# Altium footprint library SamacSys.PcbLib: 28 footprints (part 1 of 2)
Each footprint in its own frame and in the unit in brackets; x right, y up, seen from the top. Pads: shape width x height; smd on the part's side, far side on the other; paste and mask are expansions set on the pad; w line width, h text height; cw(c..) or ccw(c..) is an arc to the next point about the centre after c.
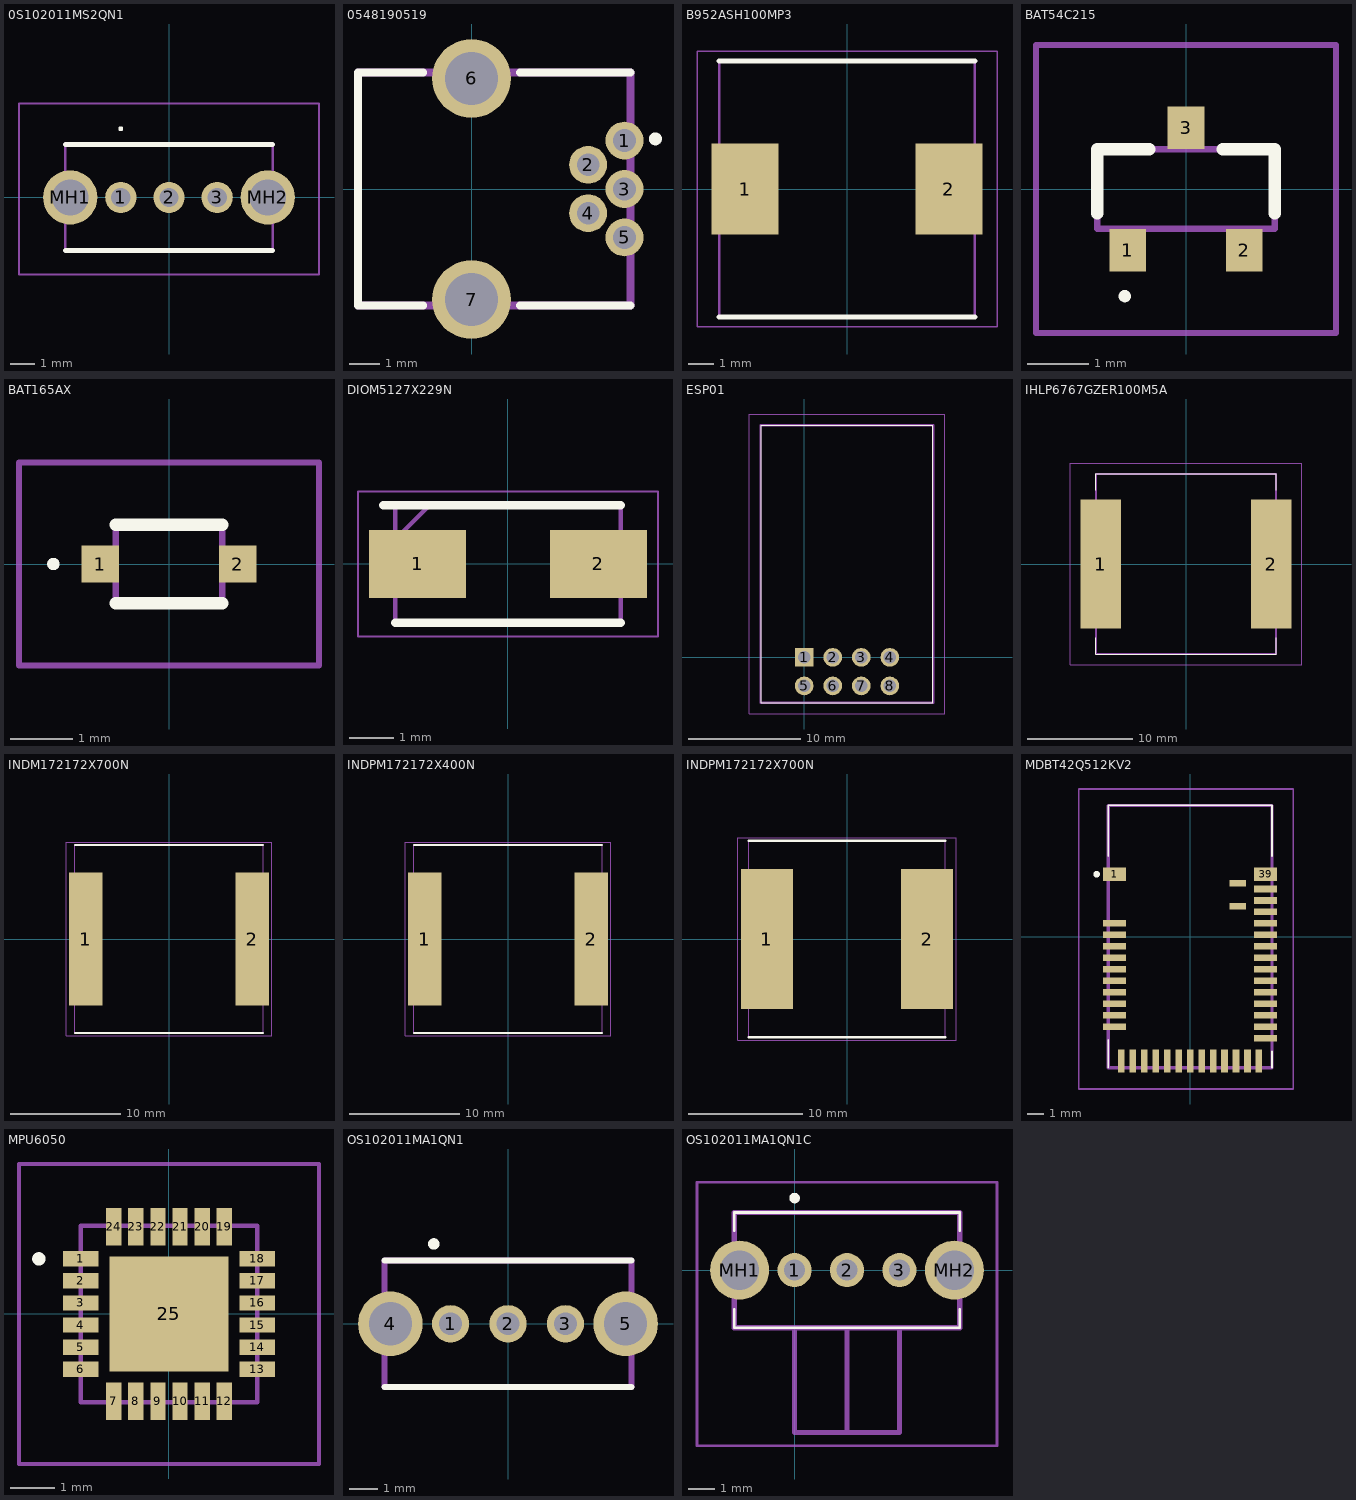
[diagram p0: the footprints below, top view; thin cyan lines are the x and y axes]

## 0S102011MS2QN1 [mm]
pads (5):
  round 1.3 hole 0.8: 1(-2,0) 2(0,0) 3(2,0)
  round 2.25 hole 1.5: MH1(-4.1,0) MH2(4.1,0)
Top Overlay:
  lines w0.1: -2,2.8 cw(c-2,2.85) -2,2.9 cw(c-2,2.85) -2,2.8
  lines w0.2: -4.3,-2.2 4.3,-2.2 ; -4.3,2.2 4.3,2.2
Mechanical 13:
  lines w0.1: -4.3,-2.15 -4.3,2.15 4.3,2.15 4.3,-2.15 -4.3,-2.15
Mechanical 15:
  lines w0.1: -6.225,-3.2 -6.225,3.9 6.225,3.9 6.225,-3.2 -6.225,-3.2
3D body "0S102011MS2QN1.stp": height 8.8, standoff -5, extent -4.745,-2.15 4.75,2.15

## 0548190519 [mm]
pads (7):
  round 1.25 hole 0.75: 1(5.05,1.6) 2(3.85,0.8) 3(5.05,0) 4(3.85,-0.8) 5(5.05,-1.6)
  round 2.6 hole 1.75: 6(0,3.65) 7(0,-3.65)
Top Overlay:
  circle w0.254: c6.071,1.655 r0.085
  lines w0.254: -1.6,-3.85 -3.75,-3.85 -3.75,3.85 -1.6,3.85 ; 1.6,-3.85 5.25,-3.85 ; 1.6,3.85 5.25,3.85
Mechanical 13:
  lines w0.254: -3.75,-3.85 5.25,-3.85 5.25,3.85 -3.75,3.85 -3.75,-3.85

## B952ASH100MP3 [mm]
pads (2):
  rect 2.65x3.6 smd: 1(-4.025,0) 2(4.025,0)
Top Overlay:
  lines w0.2: -5.05,-5.05 5.05,-5.05 ; -5.05,5.05 5.05,5.05
Mechanical 13:
  lines w0.1: -5.05,-5.05 5.05,-5.05 5.05,5.05 -5.05,5.05 -5.05,-5.05
Mechanical 15:
  lines w0.05: -5.925,-5.45 5.925,-5.45 5.925,5.45 -5.925,5.45 -5.925,-5.45
3D body "#B952AS-H-100M=P3.stp": height 4.9, standoff 0, extent -5.085,-5.05 5.085,5.05

## BAT54C215 [mm]
pads (3):
  rect 0.6x0.7 smd: 1(-0.95,-1) 2(0.95,-1) 3(0,1)
Top Overlay:
  lines w0.1: -1,-1.8 cw(c-1,-1.75) -1,-1.7 cw(c-1,-1.75) -1,-1.8
  lines w0.2: -1.45,-0.4 -1.45,0.65 -0.6,0.65 ; 0.6,0.65 1.45,0.65 1.45,-0.4
Mechanical 13:
  lines w0.1: -1.45,-0.65 -1.45,0.65 1.45,0.65 1.45,-0.65 -1.45,-0.65
Mechanical 15:
  lines w0.1: -2.45,-2.35 -2.45,2.35 2.45,2.35 2.45,-2.35 -2.45,-2.35
3D body "BAT54C,215.stp": height 0.95, standoff 0, extent -1.452,-1.201 1.448,1.199

## BAT165AX [mm]
pads (2):
  rect 0.6x0.6 smd: 1(-1.1,0) 2(1.1,0)
Top Overlay:
  lines w0.1: -1.9,0 cw(c-1.85,0) -1.8,0 cw(c-1.85,0) -1.9,0
  lines w0.2: -0.85,-0.625 0.85,-0.625 ; -0.85,0.625 0.85,0.625
Mechanical 13:
  lines w0.1: -0.85,-0.625 -0.85,0.625 0.85,0.625 0.85,-0.625 -0.85,-0.625
Mechanical 15:
  lines w0.1: -2.4,-1.625 -2.4,1.625 2.4,1.625 2.4,-1.625 -2.4,-1.625
3D body "BAT165AX.stp": height 0.93, standoff 0, extent -1.244,-0.623 1.245,0.627

## DIOM5127X229N [mm]
pads (2):
  rect 2.2x1.55 smd: 1(-2.05,0) 2(2.05,0)
Top Overlay:
  lines w0.2: -2.825,1.332 2.552,1.332 ; -2.552,-1.332 2.552,-1.332
Mechanical 13:
  lines w0.1: -2.552,0.558 -1.778,1.332 ; -2.552,-1.332 -2.552,1.332 2.552,1.332 2.552,-1.332 -2.552,-1.332
Mechanical 15:
  lines w0.05: -3.4,-1.645 -3.4,1.645 3.4,1.645 3.4,-1.645 -3.4,-1.645
3D body "ES1D-E3_61T.stp": height 2.29, standoff 0, extent -2.552,-1.332 2.552,1.332

## ESP01 [mm]
pads (8):
  rect 1.665x1.665 hole 1.11: 1(0,0)
  round 1.665 hole 1.11: 2(2.54,0) 3(5.08,0) 4(7.62,0) 5(0,-2.54) 6(2.54,-2.54) 7(5.08,-2.54) 8(7.62,-2.54)
Top Overlay:
  lines w0.1: -3.81,-4.04 -3.81,20.66 11.43,20.66 11.43,-4.04 -3.81,-4.04
Mechanical 13:
  lines w0.2: -3.89,-4.04 -3.89,20.66 11.51,20.66 11.51,-4.04 -3.89,-4.04
Mechanical 15:
  lines w0.1: -4.89,-5.04 -4.89,21.66 12.51,21.66 12.51,-5.04 -4.89,-5.04
3D body "ESP-01.stp": height 2.75, standoff 0, extent -3.56,-3.98 10.84,20.72

## IHLP6767GZER100M5A [mm]
pads (2):
  rect 3.825x12.32 smd: 1(-8.123,0) 2(8.123,0)
Top Overlay:
  lines w0.1: -8.575,-7 -8.575,-8.575 8.575,-8.575 8.575,-7 ; -8.575,7 -8.575,8.575 8.575,8.575 8.575,7
Mechanical 13:
  lines w0.2: -8.575,-8.575 -8.575,8.575 8.575,8.575 8.575,-8.575 -8.575,-8.575
Mechanical 15:
  lines w0.1: -11.035,-9.575 -11.035,9.575 11.035,9.575 11.035,-9.575 -11.035,-9.575
3D body "IHLP6767GZER100M5A.stp": height 6.89, standoff 0, extent -8.584,-8.592 8.591,8.584

## INDM172172X700N [mm]
pads (2):
  rect 3.05x12.15 smd: 1(-7.6,0) 2(7.6,0)
Top Overlay:
  lines w0.2: -8.575,-8.575 8.575,-8.575 ; -8.575,8.575 8.575,8.575
Mechanical 13:
  lines w0.1: -8.575,-8.575 -8.575,8.575 8.575,8.575 8.575,-8.575 -8.575,-8.575
Mechanical 15:
  lines w0.05: -9.375,-8.825 -9.375,8.825 9.375,8.825 9.375,-8.825 -9.375,-8.825
3D body "IHLP6767GZER101M11.stp": height 6.89, standoff 0, extent -8.584,-8.592 8.591,8.584

## INDPM172172X400N [mm]
pads (2):
  rect 3.05x12.15 smd: 1(-7.6,0) 2(7.6,0)
Top Overlay:
  lines w0.2: -8.575,-8.575 8.575,-8.575 ; -8.575,8.575 8.575,8.575
Mechanical 13:
  lines w0.1: -8.575,-8.575 -8.575,8.575 8.575,8.575 8.575,-8.575 -8.575,-8.575
Mechanical 15:
  lines w0.05: -9.375,-8.825 -9.375,8.825 9.375,8.825 9.375,-8.825 -9.375,-8.825
3D body "IHLP6767DZER4R7M01.stp": height 3.91, standoff 0, extent -8.584,-8.592 8.591,8.584

## INDPM172172X700N [mm]
pads (2):
  rect 4.55x12.2 smd: 1(-7,0) 2(7,0)
Top Overlay:
  lines w0.2: -8.575,-8.575 8.575,-8.575 ; -8.575,8.575 8.575,8.575
Mechanical 13:
  lines w0.1: -8.575,-8.575 -8.575,8.575 8.575,8.575 8.575,-8.575 -8.575,-8.575
Mechanical 15:
  lines w0.05: -9.525,-8.825 -9.525,8.825 9.525,8.825 9.525,-8.825 -9.525,-8.825
3D body "1234772.stp": height 7, standoff 0, extent -8.575,-8.575 8.575,8.575

## MDBT42Q512KV2 [mm]
pads (41):
  rect 1.4x0.8 smd: 1(-4.6,3.8) 39(4.6,3.8)
  rect 1.4x0.4 smd: 2(-4.6,0.8) 3(-4.6,0.1) 4(-4.6,-0.6) 5(-4.6,-1.3) 6(-4.6,-2) 7(-4.6,-2.7) 8(-4.6,-3.4) 9(-4.6,-4.1) 10(-4.6,-4.8) 11(-4.6,-5.5) 25(4.6,-6.2) 26(4.6,-5.5) 27(4.6,-4.8) 28(4.6,-4.1) 29(4.6,-3.4) 30(4.6,-2.7) 31(4.6,-2) 32(4.6,-1.3) 33(4.6,-0.6) 34(4.6,0.1) 35(4.6,0.8) 36(4.6,1.5) 37(4.6,2.2) 38(4.6,2.9)
  rect 0.4x1.4 smd: 12(-4.2,-7.6) 13(-3.5,-7.6) 14(-2.8,-7.6) 15(-2.1,-7.6) 16(-1.4,-7.6) 17(-0.7,-7.6) 18(0,-7.6) 19(0.7,-7.6) 20(1.4,-7.6) 21(2.1,-7.6) 22(2.8,-7.6) 23(3.5,-7.6) 24(4.2,-7.6)
  rect 1x0.4 smd: 40(2.9,3.25) 41(2.9,1.85)
Top Overlay:
  lines w0.1: -5,-8 -5,-6.3 ; -5,4.9 -5,8 4.9,8 5,8 5,4.9 ; 5,-8 5,-7
  lines w0.2: -5.7,3.7 cw(c-5.7,3.8) -5.7,3.9 cw(c-5.7,3.8) -5.7,3.7
Mechanical 13:
  lines w0.2: -5,-8 -5,8 5,8 5,-8 -5,-8
Mechanical 15:
  lines w0.1: -6.8,-9.3 -6.8,9 6.3,9 6.3,-9.3 -6.8,-9.3
3D body "MDBT42Q-512KV2.stp": height 2.3, standoff 0, extent -5,-8 5,8

## MPU6050 [mm]
pads (25):
  rect 0.8x0.35 smd: 1(-2,1.25) 2(-2,0.75) 3(-2,0.25) 4(-2,-0.25) 5(-2,-0.75) 6(-2,-1.25) 13(2,-1.25) 14(2,-0.75) 15(2,-0.25) 16(2,0.25) 17(2,0.75) 18(2,1.25)
  rect 0.35x0.85 smd: 7(-1.25,-1.975) 8(-0.75,-1.975) 9(-0.25,-1.975) 10(0.25,-1.975) 11(0.75,-1.975) 12(1.25,-1.975) 19(1.25,1.975) 20(0.75,1.975) 21(0.25,1.975) 22(-0.25,1.975) 23(-0.75,1.975) 24(-1.25,1.975)
  rect 2.7x2.6 smd: 25(0,0)
Top Overlay:
  lines w0.2: -3,1.25 ccw(c-2.95,1.25) -2.9,1.25 ; -3,1.25 cw(c-2.95,1.25) -2.9,1.25 ; -3,1.25 ccw(c-2.95,1.25) -2.9,1.25
Mechanical 13:
  lines w0.1: -2,-2 -2,2 2,2 2,-2 -2,-2
Mechanical 15:
  lines w0.1: -3.4,-3.4 -3.4,3.4 3.4,3.4 3.4,-3.4 -3.4,-3.4
3D body "MPU-6050.stp": height 0.88, standoff -0.02, extent -2,-2 2,2

## OS102011MA1QN1 [mm]
pads (5):
  round 1.3 hole 0.8: 1(-2,0) 2(0,0) 3(2,0)
  round 2.25 hole 1.5: 4(-4.1,0) 5(4.1,0)
Top Overlay:
  circle w0.2: c-2.583,2.781 r0.099
  lines w0.2: -4.3,-2.2 4.3,-2.2 ; -4.3,2.2 4.3,2.2
Mechanical 13:
  lines w0.2: -4.3,-2.2 -4.3,2.2 4.3,2.2 4.3,-2.2 -4.3,-2.2
3D body "OS102011MA1QN1.stp": height 4.59, standoff -3.01, extent -4.301,-6.215 4.299,2.185

## OS102011MA1QN1C [mm]
pads (5):
  round 1.3 hole 0.8: 1(0,0) 2(2,0) 3(4,0)
  round 2.25 hole 1.5: MH1(-2.1,0) MH2(6.1,0)
Top Overlay:
  lines w0.1: -2.3,-1.5 -2.3,-2.2 6.3,-2.2 6.3,-1.5 ; -2.3,1.5 -2.3,2.2 6.3,2.2 6.3,1.5
  lines w0.2: -0.1,2.75 cw(c0,2.75) 0.1,2.75 cw(c0,2.75) -0.1,2.75
Mechanical 13:
  lines w0.2: 2,-6.2 4,-6.2 4,-2.2 2,-2.2 ; 2,-6.2 2,-2.2 ; 2,-6.2 0,-6.2 0,-2.2 2,-2.2 ; 2,-6.2 2,-2.2 ; -2.3,-2.2 -2.3,2.2 6.3,2.2 6.3,-2.2 -2.3,-2.2
Mechanical 15:
  lines w0.1: -3.725,-6.7 -3.725,3.35 7.725,3.35 7.725,-6.7 -3.725,-6.7
3D body "OS102011MA1QN1C.stp": height 4.6, standoff -3, extent -2.3,-6.22 6.3,2.18

## PCBComponent_1 [mm]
